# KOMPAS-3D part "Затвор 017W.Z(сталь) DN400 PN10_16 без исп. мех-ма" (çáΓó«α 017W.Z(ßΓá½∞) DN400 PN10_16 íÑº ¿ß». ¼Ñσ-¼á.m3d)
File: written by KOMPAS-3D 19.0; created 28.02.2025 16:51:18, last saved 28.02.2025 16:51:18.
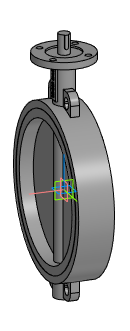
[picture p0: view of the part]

Document properties: Автор: Евгений; Полное имя файла: E:\Dendor Работа Сачек\3D для проекитирвщиков\1.5 Тип 017W.Z Сталь Затвор дисковый поворотный Межфланцевый\stp_Тип 017W.Z(сталь). Затвор без исполн. механизма\Затвор 017W.Z(сталь) DN400 PN10_16 без исп. мех-ма.m3d

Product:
- Part/product: Затвор 017W.Z(сталь) DN400 PN10_16 без исп. мех-ма

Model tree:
1. Операция без истории:1  (labels: Затвор 017W.Z(сталь) DN400 PN10_16 без исп. мех-ма)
